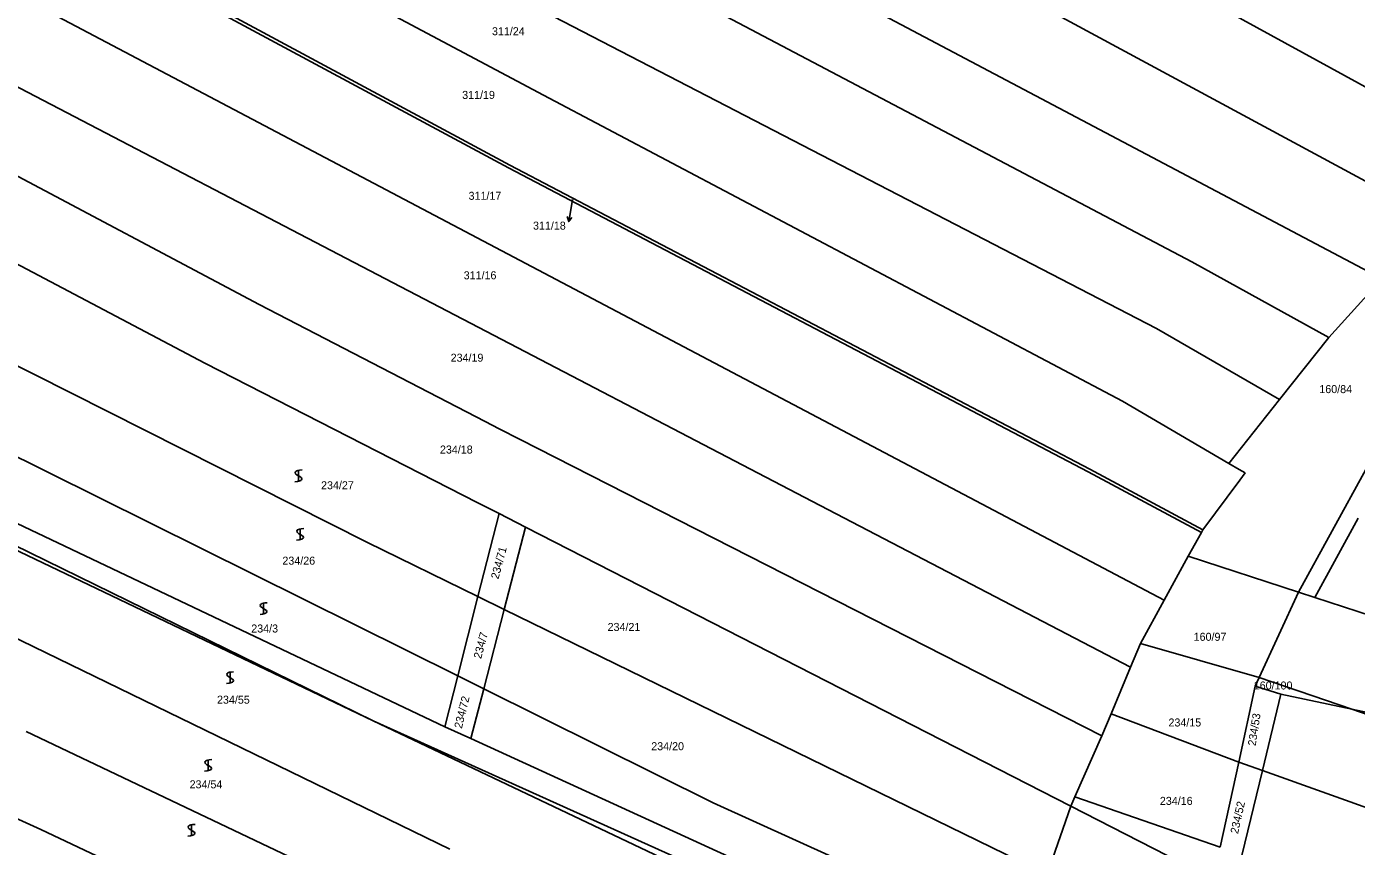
# Model space of a CAD drawing. Extents: x -580630 to -576196, y -1189024 to -1183567.
# Drawn here: x -579815.7 to -579533.2, y -1186633 to -1186458.9 of the extents above; entities that cross this region are included whole.
import ezdxf

# ---------------------------------------------------------------- set-up
doc = ezdxf.new("R2010")
doc.units = 0
for name, color, linetype in [('Vrstva 1', 7, 'Continuous'), ('Vrstva 16', 7, 'Continuous'), ('Vrstva 18', 7, 'Continuous'), ('Vrstva 25', 7, 'Continuous'), ('Vrstva 6', 7, 'Continuous')]:
    doc.layers.add(name, color=color, linetype=linetype)

msp = doc.modelspace()

# ---------------------------------------------------------------- linework, layer by layer
at = {"layer": 'Vrstva 1'}
for p, q in [((-579705.84, -1186473.49), (-579808.31, -1186418.94)), ((-579815.57, -1186433.93), (-579713.31, -1186488.94)), ((-579713, -1186488.35), (-579815.26, -1186433.34)), ((-579574.05, -1186580.71), (-579814.2, -1186454.11)), ((-579841.24, -1186459.45), (-579647.07, -1186560.65)), ((-579582.89, -1186538.51), (-579705.84, -1186473.49)), ((-579766.24, -1186517.95), (-579837.85, -1186479.99)), ((-579856.62, -1186488.93), (-579777.8, -1186530.38)), ((-579713.31, -1186488.94), (-579590.15, -1186553.51)), ((-579589.83, -1186552.92), (-579713, -1186488.35)), ((-579539.04, -1186524.96), (-579530.3, -1186515.24)), ((-579718.27, -1186542.82), (-579766.24, -1186517.95)), ((-579726.8, -1186607.62), (-579901.81, -1186524.48)), ((-579549.54, -1186538.16), (-579539.04, -1186524.96)), ((-579742.03, -1186606.4), (-579902.47, -1186529.66)), ((-579777.8, -1186530.38), (-579719.81, -1186560.04)), ((-579560.31, -1186551.7), (-579582.89, -1186538.51)), ((-579549.54, -1186538.16), (-579560.31, -1186551.7)), ((-579715.3, -1186544.33), (-579718.27, -1186542.82)), ((-579710.8, -1186546.63), (-579715.3, -1186544.33)), ((-579587.26, -1186609.58), (-579710.8, -1186546.63)), ((-579590.15, -1186553.51), (-579566.11, -1186566.36)), ((-579565.79, -1186565.78), (-579589.83, -1186552.92)), ((-579558.09, -1186552.99), (-579560.31, -1186551.7)), ((-579556.83, -1186553.73), (-579558.09, -1186552.99)), ((-579557.96, -1186555.25), (-579556.83, -1186553.73)), ((-579531.19, -1186552.99), (-579545.52, -1186579.07)), ((-579565.79, -1186565.78), (-579557.96, -1186555.25)), ((-579719.81, -1186560.04), (-579715.31, -1186562.34)), ((-579715.31, -1186562.34), (-579719.79, -1186579.99)), ((-579715.31, -1186562.34), (-579709.69, -1186565.22)), ((-579647.07, -1186560.65), (-579581.19, -1186594.98)), ((-579709.69, -1186565.22), (-579714.2, -1186582.7)), ((-579709.69, -1186565.22), (-579593.83, -1186624.48)), ((-579542.01, -1186580.21), (-579532.82, -1186563.31)), ((-579566.11, -1186566.36), (-579568.93, -1186571.42)), ((-579566.11, -1186566.36), (-579565.79, -1186565.78)), ((-579568.93, -1186571.42), (-579574.05, -1186580.71)), ((-579545.52, -1186579.07), (-579568.93, -1186571.42)), ((-579553.86, -1186597.2), (-579545.52, -1186579.07)), ((-579542.01, -1186580.21), (-579545.52, -1186579.07)), ((-579719.79, -1186579.99), (-579724.06, -1186596.82)), ((-579574.05, -1186580.71), (-579579.09, -1186589.92)), ((-579542.01, -1186580.21), (-579444.84, -1186611.95)), ((-579714.2, -1186582.7), (-579718.55, -1186599.56)), ((-579579.09, -1186589.92), (-579581.19, -1186594.98)), ((-579553.86, -1186597.2), (-579579.09, -1186589.92)), ((-579581.19, -1186594.98), (-579585.29, -1186604.85)), ((-579724.06, -1186596.82), (-579726.8, -1186607.62)), ((-579558.19, -1186615.14), (-579554.69, -1186599.02)), ((-579554.69, -1186599.02), (-579553.86, -1186597.2)), ((-579549.26, -1186600.69), (-579554.69, -1186599.02)), ((-579718.55, -1186599.56), (-579721.28, -1186610.14)), ((-579553.18, -1186616.92), (-579549.26, -1186600.69)), ((-579549.26, -1186600.69), (-579534.21, -1186603.9)), ((-579585.29, -1186604.85), (-579587.26, -1186609.58)), ((-579558.19, -1186615.14), (-579585.29, -1186604.85)), ((-579534.21, -1186603.9), (-579398.05, -1186632.93)), ((-579671.4, -1186638.2), (-579742.03, -1186606.4)), ((-579721.28, -1186610.14), (-579726.8, -1186607.62)), ((-579606.27, -1186662.7), (-579721.28, -1186610.14)), ((-579587.26, -1186609.58), (-579593.03, -1186622.53)), ((-579562.12, -1186633.22), (-579558.19, -1186615.14)), ((-579557.54, -1186634.97), (-579553.18, -1186616.92)), ((-579593.03, -1186622.53), (-579593.83, -1186624.48)), ((-579593.83, -1186624.48), (-579563.58, -1186639.95)), ((-579562.12, -1186633.22), (-579593.03, -1186622.53))]:
    msp.add_line(p, q, dxfattribs=at)
at = {"layer": 'Vrstva 16'}
for p in [(-579700.482, -1186500.346), (-579699.67, -1186495.67)]:
    msp.add_line(p, (-579699.97, -1186497.39), dxfattribs=at)
msp.add_lwpolyline([(-579699.819, -1186499.446), (-579700.482, -1186500.346), (-579700.804, -1186499.275)], dxfattribs=at)
at = {"layer": 'Vrstva 25'}
for points in [[(-579757.15, -1186553.09), (-579757.66, -1186553.15), (-579758.01, -1186553.2), (-579758.25, -1186553.28), (-579758.43, -1186553.39), (-579758.55, -1186553.48), (-579758.6, -1186553.65), (-579758.55, -1186553.88), (-579758.16, -1186554.2), (-579757.6, -1186554.51), (-579757.25, -1186554.78), (-579757.18, -1186554.98), (-579757.25, -1186555.18), (-579757.41, -1186555.31), (-579757.6, -1186555.38), (-579758.13, -1186555.51), (-579758.65, -1186555.58)], [(-579757.9, -1186555.59), (-579757.9, -1186554.32), (-579757.9, -1186553.09)], [(-579756.8, -1186565.52), (-579757.31, -1186565.58), (-579757.66, -1186565.63), (-579757.9, -1186565.71), (-579758.08, -1186565.82), (-579758.2, -1186565.91), (-579758.25, -1186566.08), (-579758.2, -1186566.31), (-579757.81, -1186566.63), (-579757.25, -1186566.94), (-579756.9, -1186567.21), (-579756.83, -1186567.41), (-579756.9, -1186567.61), (-579757.06, -1186567.74), (-579757.25, -1186567.81), (-579757.78, -1186567.94), (-579758.3, -1186568.01)], [(-579757.55, -1186568.02), (-579757.55, -1186566.75), (-579757.55, -1186565.52)], [(-579764.57, -1186581.28), (-579765.08, -1186581.34), (-579765.43, -1186581.39), (-579765.67, -1186581.47), (-579765.85, -1186581.58), (-579765.97, -1186581.67), (-579766.02, -1186581.84), (-579765.97, -1186582.07), (-579765.58, -1186582.39), (-579765.02, -1186582.7), (-579764.67, -1186582.97), (-579764.6, -1186583.17), (-579764.67, -1186583.37), (-579764.83, -1186583.5), (-579765.02, -1186583.57), (-579765.55, -1186583.7), (-579766.07, -1186583.77)], [(-579765.32, -1186583.78), (-579765.32, -1186582.51), (-579765.32, -1186581.28)], [(-579771.67, -1186595.94), (-579772.18, -1186596), (-579772.53, -1186596.05), (-579772.77, -1186596.13), (-579772.95, -1186596.24), (-579773.07, -1186596.33), (-579773.12, -1186596.5), (-579773.07, -1186596.73), (-579772.68, -1186597.05), (-579772.12, -1186597.36), (-579771.77, -1186597.63), (-579771.7, -1186597.83), (-579771.77, -1186598.03), (-579771.93, -1186598.16), (-579772.12, -1186598.23), (-579772.65, -1186598.36), (-579773.17, -1186598.43)], [(-579772.42, -1186598.44), (-579772.42, -1186597.17), (-579772.42, -1186595.94)], [(-579776.33, -1186614.58), (-579776.84, -1186614.64), (-579777.19, -1186614.69), (-579777.43, -1186614.77), (-579777.61, -1186614.88), (-579777.73, -1186614.97), (-579777.78, -1186615.14), (-579777.73, -1186615.37), (-579777.34, -1186615.69), (-579776.78, -1186616), (-579776.43, -1186616.27), (-579776.36, -1186616.47), (-579776.43, -1186616.67), (-579776.59, -1186616.8), (-579776.78, -1186616.87), (-579777.31, -1186617), (-579777.83, -1186617.07)], [(-579777.08, -1186617.08), (-579777.08, -1186615.81), (-579777.08, -1186614.58)], [(-579779.88, -1186628.35), (-579780.39, -1186628.41), (-579780.74, -1186628.46), (-579780.98, -1186628.54), (-579781.16, -1186628.65), (-579781.28, -1186628.74), (-579781.33, -1186628.91), (-579781.28, -1186629.14), (-579780.89, -1186629.46), (-579780.33, -1186629.77), (-579779.98, -1186630.04), (-579779.91, -1186630.24), (-579779.98, -1186630.44), (-579780.14, -1186630.57), (-579780.33, -1186630.64), (-579780.86, -1186630.77), (-579781.38, -1186630.84)], [(-579780.63, -1186630.85), (-579780.63, -1186629.58), (-579780.63, -1186628.35)]]:
    msp.add_lwpolyline(points, dxfattribs=at)
at = {"layer": 'Vrstva 6'}
for p, q in [((-579839.4, -1186347.64), (-579528.18, -1186512.31)), ((-579568.19, -1186508.91), (-579712.48, -1186432.8)), ((-579589.05, -1186440.04), (-579508.09, -1186484.51)), ((-579718.2, -1186449.29), (-579575.66, -1186523.03)), ((-579518.37, -1186498.73), (-579605.54, -1186451.66)), ((-579897.22, -1186490.83), (-579743.26, -1186568.53)), ((-579539.04, -1186524.96), (-579568.19, -1186508.91)), ((-579575.66, -1186523.03), (-579549.54, -1186538.16)), ((-579864.43, -1186527.15), (-579724.06, -1186596.82)), ((-579866.56, -1186545.4), (-579742.03, -1186606.4)), ((-579867.69, -1186564.63), (-579725.79, -1186633.63)), ((-579743.26, -1186568.53), (-579719.79, -1186579.99)), ((-579719.79, -1186579.99), (-579714.2, -1186582.7)), ((-579714.2, -1186582.7), (-579598.89, -1186639)), ((-579906.54, -1186587.25), (-579812.61, -1186629.43)), ((-579724.06, -1186596.82), (-579718.55, -1186599.56)), ((-579553.86, -1186597.2), (-579534.21, -1186603.9)), ((-579718.55, -1186599.56), (-579669.82, -1186623.77)), ((-579534.21, -1186603.9), (-579501.09, -1186615.19)), ((-579742.03, -1186606.4), (-579671.84, -1186639.68)), ((-579815.73, -1186608.63), (-579681.55, -1186672.42)), ((-579558.19, -1186615.14), (-579553.18, -1186616.92)), ((-579553.18, -1186616.92), (-579521.85, -1186628.09)), ((-579669.82, -1186623.77), (-579603.51, -1186653.84)), ((-579598.35, -1186637.27), (-579593.83, -1186624.48)), ((-579812.61, -1186629.43), (-579691.07, -1186686.93))]:
    msp.add_line(p, q, dxfattribs=at)

# ---------------------------------------------------------------- texts
at = {"layer": 'Vrstva 16'}
msp.add_text('311/18', height=1.7, dxfattribs=at).set_placement((-579708.089, -1186502.05))
at = {"layer": 'Vrstva 18'}
for s, height, p in [('311/24', 1.7, (-579716.807, -1186460.77)), ('311/19', 1.7, (-579723.135, -1186474.29)), ('311/17', 1.7, (-579721.775, -1186495.72)), ('311/18', 0.1, (-579699.857, -1186495.67)), ('311/16', 1.7, (-579722.815, -1186512.6)), ('234/19', 1.7, (-579725.585, -1186530.1)), ('160/84', 1.7, (-579541.078, -1186536.77)), ('234/18', 1.7, (-579727.855, -1186549.6)), ('234/27', 1.7, (-579753.107, -1186557.19)), ('234/26', 1.7, (-579761.317, -1186573.2)), ('234/3', 1.7, (-579767.931, -1186587.61)), ('234/21', 1.7, (-579692.249, -1186587.28)), ('160/97', 1.7, (-579567.771, -1186589.37)), ('160/100', 1.7, (-579555.006, -1186599.71)), ('234/55', 1.7, (-579775.207, -1186602.73)), ('234/15', 1.7, (-579573.122, -1186607.57)), ('234/20', 1.7, (-579682.974, -1186612.61)), ('234/54', 1.7, (-579781.03, -1186620.7)), ('234/16', 1.7, (-579574.945, -1186624.22))]:
    msp.add_text(s, height=height, dxfattribs=at).set_placement(p)
for s, rotation, p in [('234/71', 75.00018, (-579715.438, -1186576.382)), ('234/7', 75.11477, (-579719.113, -1186593.304)), ('234/72', 76.14609, (-579723.214, -1186608.121)), ('234/53', 81.13083, (-579554.611, -1186611.784)), ('234/52', 77.46389, (-579558.356, -1186630.469))]:
    msp.add_text(s, height=1.7, rotation=rotation, dxfattribs=at).set_placement(p)

doc.saveas('drawing.dxf')
